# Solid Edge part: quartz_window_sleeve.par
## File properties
Title: Quatz Window Sleeve
Subject: SHMS Heavy Gas Cerenkov
Author: Lee Sichello
Template: Metric Part.par
Last saved by: Lee
Revision: 47
Application: Solid Edge
Material: Aluminum
Face Style: Model Default
Coef. of Thermal Exp: 0.0
Thermal Conductivity: 0.0
Specific Heat: 0.0
Modulus of Elasticity: 0.0
Poisson's Ratio: 0.0
Yield Stress: 0.0
Ultimate Stress: 0.0
Elongation: 0.0
Manager: Garth Huber
Accuracy: 0.990
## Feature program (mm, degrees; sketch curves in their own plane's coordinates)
sketch for "unnamed Protrusion 1" #1 plane through (0, 0, 0) normal (0, 0, 1) x-axis (1, 0, 0)
sketch for "unnamed Protrusion 1" #2 plane through (0, 0, 0) normal (0, 0, 1) x-axis (1, 0, 0)
  circle centre (0, 0) radius 82
extrude "unnamed Protrusion 1" add finite 12.7 along +normal
sketch for "ExtrudedProtrusion_4" #1 plane through (0, 0, 12.7) normal (0, 0, 1) x-axis (0, 1, 0)
  circle centre (0, 0) radius 109.5375
sketch for "ExtrudedProtrusion_4" #2 plane through (0, 0, 12.7) normal (0, 0, 1) x-axis (0, 1, 0)
  circle centre (0, 0) radius 91
extrude "ExtrudedProtrusion_4" add finite 431.8 along +normal
sketch for "Hole_21" plane through (0, 0, 0) normal (0, 0, -1) x-axis (0, 1, 0)
  hole centre (100.269, 0) bore radius 3.3235
hole "Hole_21" nominal diameter 8 finite
sketch for "unnamed Hole 1" plane through (0, 0, 0) normal (0, 0, -1) x-axis (0, 1, 0)
  hole centre (70.9009, 70.9009) bore radius 3.3235
hole "unnamed Hole 1" finite
sketch for "unnamed Hole 2" plane through (0, 0, 0) normal (0, 0, -1) x-axis (0, 1, 0)
  hole centre (0, 100.269) bore radius 3.3235
hole "unnamed Hole 2" finite
sketch for "unnamed Hole 3" plane through (0, 0, 0) normal (0, 0, -1) x-axis (0, 1, 0)
  hole centre (-70.9009, 70.9009) bore radius 3.3235
hole "unnamed Hole 3" finite
sketch for "unnamed Hole 4" plane through (0, 0, 0) normal (0, 0, -1) x-axis (0, 1, 0)
  hole centre (0, -100.269) bore radius 3.3235
hole "unnamed Hole 4" finite
sketch for "unnamed Hole 5" plane through (0, 0, 0) normal (0, 0, -1) x-axis (0, 1, 0)
  hole centre (-100.269, 0) bore radius 3.3235
hole "unnamed Hole 5" finite
sketch for "unnamed Hole 6" plane through (0, 0, 0) normal (0, 0, -1) x-axis (0, 1, 0)
  hole centre (-70.9009, -70.9009) bore radius 3.3235
hole "unnamed Hole 6" finite
sketch for "unnamed Hole 7" plane through (0, 0, 0) normal (0, 0, -1) x-axis (0, 1, 0)
hole "unnamed Hole 7" finite
pattern "unnamed Pattern 1" of "Hole_21", "unnamed Hole 1", "unnamed Hole 2", "unnamed Hole 3", "unnamed Hole 4", "unnamed Hole 5", "unnamed Hole 6", "unnamed Hole 7"
fillet "Round_2" radius 1.5
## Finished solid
Body 1: solid body, 23 faces, 23 edges, 0 vertices.
  Faces by surface: cylinder 11, plane 11, torus 1
  Edges by curve: circle 23
Bounding box of the edges (mm; curved faces can reach further): 219.075 x 219.075 x 444.500, from (-109.5375, -109.5375, 0) to (109.5375, 109.5375, 444.5).
Cylindrical faces by radius (mm): R3.3235 x8, R82 x1, R91 x1, R109.5375 x1
Toroidal faces (ring radius, tube radius in mm): R83.5 r1.5 x1
Planar faces by outward normal: +z 2, -z 9
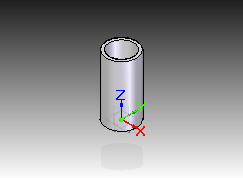
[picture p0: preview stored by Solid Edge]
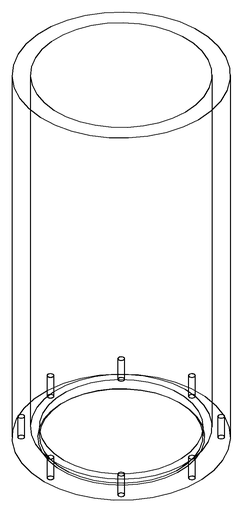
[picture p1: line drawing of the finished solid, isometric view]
